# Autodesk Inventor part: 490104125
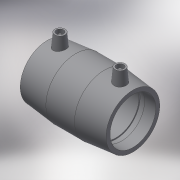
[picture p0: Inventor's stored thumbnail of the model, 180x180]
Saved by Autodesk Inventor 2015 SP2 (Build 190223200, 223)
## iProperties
Created: 2017-06
Part Number: 490104125
Material: Generic
Description: PLASSON COUPLER 125-125
Document SubType Name: Modeling
Designer: KIM
Mass: 1006.52 g
Surface Area: 1660.68 cm^2
Volume: 1006.52 cm^3
Density: 1 g/cm^3
Appearance: Default
Author: KIM
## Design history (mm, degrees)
derived "490104.ipt"
feature "Solid1::490104.ipt"
tag "TaggingFeature1"
body "Solid1"
other parameters: "d0" = 173, "d1" = 125, "d2" = 157, "d3" = 85, "d4" = 57.66667, "d5" = 141.3, "d6" = 118.75, "d7" = 125, "d8" = 168 deg, "d10" = 34, "d11" = 11.33333, "d13" = 173, "d14" = 17.6296, "d15" = 85, "d16" = 85, "d17" = 118.75, "d18" = 125, "d19" = 3.52592, "d20" = 168 deg, "d22" = 147.58, "d23" = 157, "d24" = 143.1526, "d25" = 135 deg, "d26" = 69.2, "d27" = 135 deg, "d29" = 87, "d30" = 14, "d31" = 60.55, "d34" = 5 deg, "d35" = 15, "d39" = 5 deg, "d41" = 4, "d42" = 14, "d43" = 0, "d45" = 4, "d46" = 14, "d47" = 0, "d48" = 3, "d49" = 0, "d50" = 3, "d51" = 0, "d52" = 24.65, "d53" = 6.1625, "d_" = 125, "L_" = 173, "L_1" = 85, "D_" = 157, "A_" = 87, "d_2" = 12
